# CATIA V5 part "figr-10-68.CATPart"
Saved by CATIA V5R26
Part number: Part1
Bounding box of the stored display mesh (mm): x -80.563 to 63.541, y -72 to 69, z -55 to 6.847
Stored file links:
  D:\_Deepak\CATIA\CATIA V5-6R2016_Deepak\Resources\Part files\Partfiles\c10_catia_v5_6r2016_prt\figr-10-68.CATPart
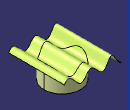
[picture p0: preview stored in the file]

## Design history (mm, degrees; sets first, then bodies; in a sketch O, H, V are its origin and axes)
Set1
  Sketch1 on xy-plane, origin (0, 0, 0), H (-1, 0, 0), V (0, -1, 0)
    circle A1 centre (0, 0) radius 45.985
  Extrude1: Element1 Sketch1, Lim1 56, Lim2 55, Direction xy-plane
  Sketch2 on zx-plane, origin (0, 0, 0), H (1, 0, 0), V (0, 0, -1)
    spline S1 through (-80.5635, 24.8913) (-73.6025, 19.8803) (-54.8525, -3.3629) (-35.1982, 19.8803) (-2.6271, -1.6506) (16.6996, 17.2854) (52.4104, -6.7877) (63.5409, 1.5862)
  Extrude2: Element1 Sketch2, Lim1 72, Lim2 69, Direction Sketch1.V
  Split1: ToCut Extrude1, Cutting Extrude2
Body1 (main body)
